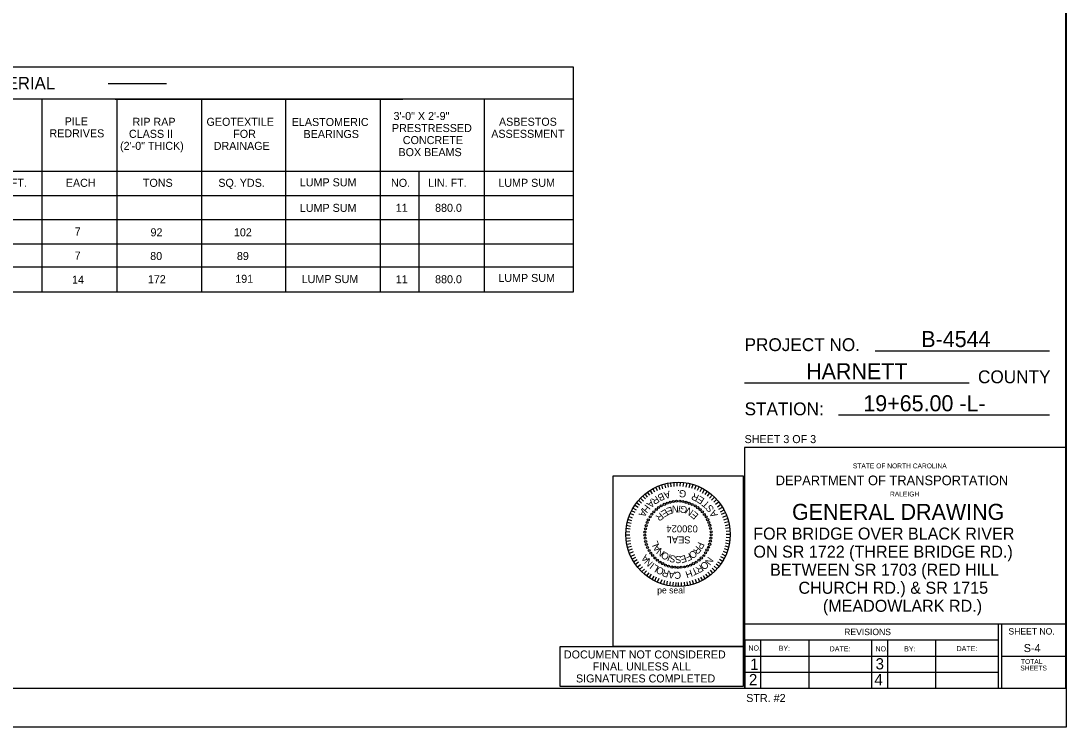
# Model space of a CAD drawing. Extents: x 985 to 1514, y -701 to -21.
# Drawn here: x 1253.7 to 1514.2, y -701.2 to -525.2 of the extents above; entities that cross this region are included whole.
import ezdxf

# ---------------------------------------------------------------- set-up
doc = ezdxf.new("R2010")
doc.units = 0
for name, color, linetype in [('Default', 7, 'Continuous'), ('Peseal', 7, 'Continuous'), ('Plan Sheet CELL', 7, 'Continuous'), ('Plot Shape CELL', 7, 'Continuous'), ('Sheet Sticker Exception Certification CELL', 7, 'Continuous'), ('Subtitle Text', 7, 'Continuous'), ('Text', 7, 'Continuous'), ('Title Text', 7, 'Continuous'), ('Typical Text General CELL', 7, 'Continuous'), ('User Information Notes', 7, 'Continuous'), ('User Information Notes CELL', 7, 'Continuous')]:
    doc.layers.add(name, color=color, linetype=linetype)

msp = doc.modelspace()

# ---------------------------------------------------------------- linework, layer by layer
at = {"layer": 'Default'}
for p, q in [((1391.43, -536.66), (1085.36, -536.66)), ((1301.25, -536.66), (1229.53, -536.66)), ((1391.43, -592.68), (1391.43, -536.66)), ((1290.03, -540.84), (1275.44, -540.84)), ((1310.78, -544.65), (1085.36, -544.65)), ((1374.09, -544.65), (1233.81, -544.65)), ((1277.19, -544.65), (1348.91, -544.65)), ((1319.64, -544.65), (1319.64, -592.68)), ((1391.43, -544.65), (1322.29, -544.65)), ((1085.36, -562.58), (1310.78, -562.58)), ((1175.28, -562.58), (1391.43, -562.58)), ((1085.36, -592.68), (1391.43, -592.68))]:
    msp.add_line(p, q, dxfattribs=at)
at = {"layer": 'Peseal'}
for p, q in [((1413.76, -641.76), (1413.44, -640.76)), ((1414.44, -641.51), (1414.19, -640.57)), ((1415.13, -641.38), (1414.94, -640.38)), ((1415.82, -641.26), (1415.69, -640.26)), ((1416.57, -641.2), (1416.51, -640.2)), ((1417.32, -641.13), (1417.32, -640.13)), ((1418.07, -641.13), (1418.13, -640.13)), ((1418.82, -641.2), (1418.94, -640.2)), ((1419.57, -641.32), (1419.76, -640.32)), ((1420.26, -641.45), (1420.51, -640.51)), ((1420.94, -641.63), (1421.26, -640.7)), ((1409.94, -643.82), (1409.32, -643.01)), ((1410.51, -643.38), (1409.94, -642.57)), ((1411.13, -643.01), (1410.57, -642.13)), ((1411.76, -642.63), (1411.26, -641.7)), ((1412.38, -642.26), (1411.94, -641.38)), ((1413.07, -642.01), (1412.69, -641.07)), ((1421.69, -641.88), (1422.01, -640.95)), ((1422.38, -642.13), (1422.76, -641.26)), ((1423.01, -642.45), (1423.44, -641.57)), ((1423.63, -642.82), (1424.13, -641.95)), ((1424.26, -643.2), (1424.82, -642.38)), ((1424.82, -643.57), (1425.38, -642.82)), ((1425.38, -644.07), (1426.01, -643.32)), ((1407.57, -646.45), (1406.69, -645.88)), ((1407.94, -645.88), (1407.13, -645.26)), ((1408.38, -645.32), (1407.63, -644.63)), ((1408.88, -644.82), (1408.13, -644.07)), ((1409.38, -644.26), (1408.76, -643.57)), ((1425.88, -644.57), (1426.63, -643.82)), ((1426.44, -645.07), (1427.13, -644.45)), ((1426.88, -645.63), (1427.69, -645.01)), ((1427.32, -646.26), (1428.13, -645.7)), ((1406.19, -649.07), (1405.26, -648.7)), ((1406.51, -648.32), (1405.57, -647.95)), ((1406.82, -647.7), (1405.88, -647.26)), ((1407.13, -647.07), (1406.26, -646.57)), ((1427.69, -646.82), (1428.57, -646.32)), ((1428.07, -647.51), (1429.01, -647.01)), ((1428.38, -648.13), (1429.32, -647.7)), ((1428.69, -648.82), (1429.63, -648.45)), ((1405.69, -651.13), (1404.69, -650.95)), ((1405.82, -650.45), (1404.82, -650.2)), ((1406.01, -649.76), (1405.01, -649.45)), ((1428.94, -649.51), (1429.88, -649.2)), ((1429.13, -650.2), (1430.13, -649.95)), ((1429.32, -650.88), (1430.26, -650.7)), ((1405.51, -652.57), (1404.51, -652.51)), ((1405.51, -653.32), (1404.51, -653.32)), ((1405.57, -651.82), (1404.57, -651.7)), ((1429.38, -651.57), (1430.38, -651.45)), ((1429.51, -652.32), (1430.51, -652.26)), ((1429.51, -653.07), (1430.51, -653.07)), ((1429.51, -653.82), (1430.51, -653.88)), ((1405.57, -654.07), (1404.57, -654.13)), ((1405.63, -654.76), (1404.63, -654.88)), ((1405.76, -655.45), (1404.76, -655.63)), ((1405.88, -656.13), (1404.94, -656.38)), ((1429.19, -655.95), (1430.13, -656.2)), ((1429.32, -655.26), (1430.32, -655.45)), ((1429.44, -654.57), (1430.38, -654.7)), ((1406.07, -656.82), (1405.13, -657.13)), ((1406.32, -657.51), (1405.38, -657.88)), ((1406.63, -658.2), (1405.76, -658.63)), ((1406.94, -658.88), (1406.07, -659.32)), ((1428.13, -658.63), (1429.07, -659.13)), ((1428.44, -658.01), (1429.38, -658.45)), ((1428.76, -657.32), (1429.69, -657.7)), ((1429.01, -656.63), (1429.94, -656.95)), ((1407.32, -659.51), (1406.51, -660.01)), ((1407.69, -660.07), (1406.88, -660.63)), ((1408.19, -660.7), (1407.38, -661.32)), ((1408.63, -661.2), (1407.88, -661.88)), ((1426.01, -661.57), (1426.76, -662.32)), ((1426.51, -661.07), (1427.26, -661.7)), ((1427.01, -660.51), (1427.76, -661.07)), ((1427.38, -659.95), (1428.26, -660.51)), ((1427.82, -659.32), (1428.69, -659.82)), ((1409.13, -661.76), (1408.44, -662.45)), ((1409.63, -662.2), (1409.01, -662.95)), ((1410.26, -662.7), (1409.63, -663.45)), ((1410.82, -663.07), (1410.26, -663.95)), ((1411.44, -663.51), (1410.94, -664.38)), ((1412.07, -663.82), (1411.63, -664.76)), ((1412.76, -664.13), (1412.32, -665.07)), ((1421.76, -664.32), (1422.13, -665.26)), ((1422.51, -664.07), (1422.88, -664.95)), ((1423.13, -663.76), (1423.57, -664.63)), ((1423.76, -663.38), (1424.26, -664.26)), ((1424.38, -663.01), (1424.94, -663.82)), ((1424.94, -662.57), (1425.57, -663.32)), ((1425.51, -662.07), (1426.13, -662.82)), ((1413.44, -664.45), (1413.07, -665.38)), ((1414.13, -664.63), (1413.88, -665.63)), ((1414.82, -664.82), (1414.63, -665.82)), ((1415.51, -664.95), (1415.38, -665.95)), ((1416.26, -665.07), (1416.13, -666.07)), ((1416.94, -665.13), (1416.88, -666.13)), ((1417.51, -665.13), (1417.51, -666.13)), ((1418.26, -665.13), (1418.32, -666.13)), ((1419.01, -665.01), (1419.13, -666.01)), ((1419.69, -664.95), (1419.88, -665.95)), ((1420.38, -664.76), (1420.63, -665.76)), ((1421.07, -664.57), (1421.38, -665.57))]:
    msp.add_line(p, q, dxfattribs=at)
for centre, radius in [((1413.32, -646.04), 0.252), ((1414.07, -645.63), 0.28), ((1414.79, -645.35), 0.238), ((1415.57, -645.13), 0.258), ((1416.35, -644.95), 0.252), ((1417.13, -644.88), 0.25), ((1417.94, -644.88), 0.25), ((1418.73, -644.95), 0.252), ((1419.51, -645.13), 0.258), ((1420.29, -645.38), 0.267), ((1421.04, -645.66), 0.238), ((1421.76, -646.04), 0.252), ((1410.54, -648.76), 0.252), ((1410.98, -648.1), 0.269), ((1411.51, -647.48), 0.244), ((1412.1, -646.95), 0.244), ((1412.66, -646.45), 0.244), ((1422.41, -646.48), 0.269), ((1423.01, -646.95), 0.265), ((1423.57, -647.51), 0.265), ((1424.07, -648.16), 0.244), ((1424.54, -648.76), 0.252), ((1409.57, -650.95), 0.258), ((1409.82, -650.16), 0.267), ((1410.1, -649.51), 0.252), ((1424.88, -649.45), 0.28), ((1425.19, -650.16), 0.267), ((1425.44, -650.88), 0.258), ((1409.26, -652.54), 0.252), ((1409.26, -653.32), 0.25), ((1409.32, -654.1), 0.252), ((1409.38, -651.73), 0.252), ((1425.63, -651.66), 0.252), ((1425.69, -654.04), 0.252), ((1425.76, -652.48), 0.252), ((1425.76, -653.26), 0.25), ((1409.44, -654.88), 0.258), ((1409.63, -655.66), 0.267), ((1409.91, -656.41), 0.238), ((1425.1, -656.35), 0.238), ((1425.38, -655.6), 0.267), ((1425.57, -654.82), 0.258), ((1410.29, -657.13), 0.252), ((1410.73, -657.82), 0.252), ((1411.19, -658.42), 0.244), ((1411.73, -659.01), 0.244), ((1423.32, -659.01), 0.265), ((1423.91, -658.42), 0.221), ((1424.35, -657.73), 0.269), ((1424.73, -657.01), 0.288), ((1412.35, -659.57), 0.244), ((1413.01, -660.04), 0.252), ((1413.69, -660.42), 0.252), ((1414.41, -660.79), 0.238), ((1415.13, -661.04), 0.228), ((1415.94, -661.26), 0.258), ((1416.73, -661.32), 0.252), ((1417.51, -661.38), 0.25), ((1418.29, -661.32), 0.252), ((1419.1, -661.23), 0.221), ((1419.88, -661.04), 0.228), ((1420.6, -660.79), 0.238), ((1421.32, -660.45), 0.28), ((1422.04, -660.04), 0.269), ((1422.73, -659.54), 0.269)]:
    msp.add_circle(centre, radius, dxfattribs=at)
at = {"layer": 'Plan Sheet CELL'}
for p, q in [((1514.1, -355.46), (1514.1, -691.46)), ((1510.1, -607.45), (1466.63, -607.45)), ((1490.1, -615.46), (1434.1, -615.46)), ((1510.1, -623.45), (1457.47, -623.45)), ((1514.1, -631.45), (1434.1, -631.45)), ((1434.1, -631.45), (1434.1, -691.46)), ((1434.1, -675.45), (1514.1, -675.45)), ((1497.31, -675.45), (1497.31, -691.46)), ((1498.1, -675.45), (1498.1, -691.46)), ((1434.1, -679.45), (1497.34, -679.45)), ((1434.15, -679.45), (1434.15, -691.46)), ((1438.1, -679.45), (1438.1, -691.46)), ((1450.1, -679.52), (1450.1, -691.52)), ((1465.71, -679.45), (1465.71, -691.56)), ((1469.72, -679.45), (1469.72, -691.47)), ((1481.72, -679.45), (1481.72, -691.47)), ((1434.1, -683.46), (1497.47, -683.46)), ((1498.1, -683.46), (1513.96, -683.46)), ((1434.1, -687.45), (1497.34, -687.45)), ((1002.1, -691.46), (1514.1, -691.46)), ((1514.24, -701.16), (1514.24, -701.16))]:
    msp.add_line(p, q, dxfattribs=at)
at = {"layer": 'Plot Shape CELL'}
msp.add_lwpolyline([(985.23, -349.16), (1514.24, -349.16), (1514.24, -701.16), (985.23, -701.16)], close=True, dxfattribs=at)
at = {"layer": 'Sheet Sticker Exception Certification CELL'}
msp.add_lwpolyline([(1388.13, -681.03), (1433.71, -681.03), (1433.71, -691.06), (1388.13, -691.06)], close=True, dxfattribs=at)
at = {"layer": 'Typical Text General CELL'}
for p, q in [((1258.89, -544.65), (1258.89, -592.68)), ((1277.59, -544.65), (1277.59, -592.68)), ((1277.59, -544.65), (1277.59, -592.68)), ((1298.77, -544.65), (1298.77, -592.68)), ((1343.23, -544.65), (1343.23, -592.68)), ((1369.19, -544.65), (1369.19, -592.68)), ((1352.89, -562.58), (1352.89, -592.68)), ((1085.36, -568.7), (1310.78, -568.7)), ((1175.28, -568.7), (1391.43, -568.7)), ((1085.36, -574.63), (1310.78, -574.63)), ((1175.28, -574.63), (1391.43, -574.63)), ((1085.36, -580.69), (1391.43, -580.69)), ((1085.36, -586.49), (1310.78, -586.49)), ((1175.28, -586.49), (1391.43, -586.49))]:
    msp.add_line(p, q, dxfattribs=at)
at = {"layer": 'User Information Notes'}
msp.add_line((1417.51, -653.13), (1417.51, -653.13), dxfattribs=at)
at = {"layer": 'User Information Notes CELL'}
msp.add_line((1417.51, -653.13), (1417.51, -653.13), dxfattribs=at)
msp.add_lwpolyline([(1401.31, -638.53), (1433.71, -638.53), (1433.71, -681.03), (1401.31, -681.03)], close=True, dxfattribs=at)
msp.add_circle((1417.51, -653.13), 13, dxfattribs=at)

# ---------------------------------------------------------------- texts
at = {"layer": 'Default'}
for s, height, p in [('TOTAL BILL OF MATERIAL', 3.1223, (1210.04, -542.22)), ('PILE', 2, (1264.62, -551.18)), ('RIP RAP', 2, (1281.55, -551.3)), ('GEOTEXTILE', 2, (1299.98, -551.3)), ('ELASTOMERIC', 2, (1321.22, -551.35)), ('3\'-0" X 2\'-9"', 2, (1346.6, -549.86)), ('ASBESTOS', 2, (1372.88, -551.29)), ('REDRIVES', 2, (1260.82, -554.18)), ('CLASS II', 2, (1280.64, -554.3)), ('FOR ', 2, (1306.64, -554.3)), ('PRESTRESSED', 2, (1346.2, -552.86)), ('ASSESSMENT', 2, (1370.95, -554.29)), ('BEARINGS', 2, (1324.16, -554.35)), ('CONCRETE', 2, (1348.91, -555.86)), ('(2\'-0" THICK)', 2, (1278.43, -557.3)), ('DRAINAGE', 2, (1301.77, -557.3)), ('BOX BEAMS', 2, (1347.83, -558.86)), ('LIN. FT.', 2, (1245.55, -566.51)), ('EACH', 2, (1264.9, -566.51)), ('TONS', 2, (1284.12, -566.51)), ('SQ. YDS.', 2, (1302.92, -566.51)), ('LUMP SUM', 2, (1323.24, -566.39)), ('NO.', 2, (1345.97, -566.51)), ('LIN. FT.', 2, (1355.18, -566.51)), ('LUMP SUM', 2, (1372.72, -566.51)), ('LUMP SUM', 2, (1323.24, -572.75)), ('LUMP SUM', 2, (1323.69, -590.5)), ('LUMP SUM', 2, (1372.72, -590.22))]:
    msp.add_text(s, height=height, dxfattribs=at).set_placement(p)
at = {"layer": 'Peseal'}
for s, height, rotation, p in [('B', 1.77, 204.8312, (1413.65, -642.71)), ('A', 1.77, 195.7955, (1415.33, -642.24)), ('.', 1.77, 182.1323, (1417.97, -642.03)), ('G', 1.77, 173.3858, (1419.65, -642.23)), ('R', 1.78, 155.458, (1422.9, -643.42)), ('E', 1.77, 147.1453, (1424.25, -644.3)), ('H', 1.77, 231.3597, (1409.4, -645.53)), ('A', 1.77, 222.3241, (1410.69, -644.36)), ('R', 1.77, 213.5776, (1412.11, -643.42)), ('N', 1.75, 178.6088, (1417.69, -646.01)), ('I', 1.75, 170.5906, (1418.32, -646.01)), ('G', 1.75, 162.5725, (1420.01, -646.38)), ('T', 1.77, 138.1096, (1425.55, -645.47)), ('S', 1.77, 129.4349, (1426.62, -646.77)), ('A', 1.77, 239.6007, (1408.39, -646.78)), ('R', 1.75, 218.6997, (1413.07, -647.57)), ('E', 1.75, 210.6815, (1414.44, -646.7)), ('E', 1.75, 194.6452, (1415.94, -646.2)), ('N', 1.75, 146.5361, (1421.51, -647.2)), ('E', 1.75, 138.5179, (1422.76, -648.26)), ('A', 1.77, 120.3993, (1427.5, -648.28)), ('030024', 1.75, 180, (1422.43, -650.88)), ('SEAL', 1.75, 180, (1420.63, -653.63)), ('L', 1.75, 110.0824, (1412.82, -655.82)), ('A', 1.75, 126.1483, (1413.44, -656.7)), ('N', 1.75, 142.2141, (1414.32, -657.45)), ('R', 1.75, 230.5765, (1422.13, -655.88)), ('P', 1.75, 246.6424, (1422.57, -654.88)), ('A', 1.75, 128.6477, (1410.51, -659.2)), ('N', 1.75, 135.6745, (1411.38, -660.13)), ('O', 1.75, 150.2471, (1415.51, -658.2)), ('I', 1.75, 158.28, (1415.88, -658.26)), ('S', 1.75, 166.313, (1417.13, -658.57)), ('S', 1.75, 182.3789, (1418.32, -658.51)), ('E', 1.75, 198.4448, (1419.32, -658.2)), ('F', 1.75, 206.4777, (1420.44, -657.7)), ('O', 1.75, 222.5436, (1421.32, -656.88)), ('N', 1.75, 234.0504, (1425.07, -658.57)), ('I', 1.75, 142.7014, (1411.82, -660.51)), ('L', 1.75, 149.7282, (1412.88, -661.2)), ('O', 1.75, 156.7551, (1414.19, -661.76)), ('T', 1.75, 205.943, (1421.94, -661.26)), ('R', 1.75, 212.9699, (1423.13, -660.57)), ('O', 1.75, 219.9967, (1424.26, -659.63)), ('R', 1.75, 163.7819, (1415.44, -662.26)), ('A', 1.75, 170.8088, (1416.82, -662.45)), ('C', 1.75, 184.8625, (1418.19, -662.38)), ('H', 1.75, 198.9162, (1420.76, -661.88))]:
    msp.add_text(s, height=height, rotation=rotation, dxfattribs=at).set_placement(p)
at = {"layer": 'Plan Sheet CELL'}
for s, height, p in [('PROJECT NO.', 3.2, (1434.1, -607.45)), ('COUNTY', 3.2, (1492.28, -615.46)), ('STATION:', 3.2, (1434.1, -623.45)), ('SHEET 3 OF 3', 2, (1434.1, -630.38)), ('STATE OF NORTH CAROLINA', 1.1999, (1461.1, -636.66)), ('DEPARTMENT OF TRANSPORTATION', 2.3999, (1441.86, -640.87)), ('RALEIGH', 1.2, (1470.34, -643.68)), ('REVISIONS', 1.6, (1458.94, -678.24)), ('SHEET NO.', 1.6, (1499.87, -678.09)), ('NO.', 1.275, (1435.05, -682.09)), ('BY:', 1.275, (1442.6, -682.15)), ('DATE:', 1.275, (1455.31, -682.29)), ('NO.', 1.275, (1466.73, -682.29)), ('BY:', 1.275, (1473.88, -682.3)), ('DATE:', 1.275, (1486.93, -682.22)), ('1', 2.8, (1435.47, -686.91)), ('3', 2.8, (1466.76, -686.78)), ('TOTAL', 1.2, (1503, -685.42)), ('SHEETS', 1.2, (1502.82, -687.04)), ('2', 2.8, (1435.18, -690.72)), ('4', 2.8, (1466.46, -690.72))]:
    msp.add_text(s, height=height, dxfattribs=at).set_placement(p)
at = {"layer": 'Sheet Sticker Exception Certification CELL'}
for s, p in [('DOCUMENT NOT CONSIDERED', (1389.07, -684.05)), ('FINAL UNLESS ALL', (1396.24, -687.04)), ('SIGNATURES COMPLETED', (1392.08, -690.03))]:
    msp.add_text(s, height=1.9955, dxfattribs=at).set_placement(p)
at = {"layer": 'Subtitle Text'}
for s, p in [('FOR BRIDGE OVER BLACK RIVER', (1436.26, -654.43)), ('ON SR 1722 (THREE BRIDGE RD.)', (1436.3, -658.93)), ('BETWEEN SR 1703 (RED HILL', (1440.45, -663.43)), ('CHURCH RD.) & SR 1715', (1447.54, -667.93)), ('(MEADOWLARK RD.)', (1453.62, -672.43))]:
    msp.add_text(s, height=3, dxfattribs=at).set_placement(p)
at = {"layer": 'Text'}
for s, p in [('11', (1347.15, -572.74)), ('880.0', (1356.95, -572.74)), ('7', (1267.12, -578.64)), ('92', (1286.02, -578.85)), ('102', (1306.81, -578.85)), ('7', (1267.12, -584.64)), ('80', (1285.94, -584.75)), ('89', (1307.55, -584.75)), ('14', (1266.46, -590.65)), ('172', (1285.36, -590.54)), ('191', (1307.14, -590.43)), ('11', (1347.15, -590.54)), ('880.0', (1356.95, -590.54)), ('S-4', (1503.7, -682.46)), ('STR. #2', (1434.51, -694.91))]:
    msp.add_text(s, height=2, dxfattribs=at).set_placement(p)
at = {"layer": 'Title Text'}
for s, p in [('B-4544', (1478.15, -606.45)), ('HARNETT', (1449.44, -614.46)), ('19+65.00 -L-', (1463.69, -622.45)), ('GENERAL DRAWING', (1445.93, -649.52))]:
    msp.add_text(s, height=4, dxfattribs=at).set_placement(p)
at = {"layer": 'User Information Notes CELL'}
msp.add_text('pe seal', height=1.6, dxfattribs=at).set_placement((1412.32, -667.84))

doc.saveas('drawing.dxf')
